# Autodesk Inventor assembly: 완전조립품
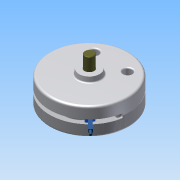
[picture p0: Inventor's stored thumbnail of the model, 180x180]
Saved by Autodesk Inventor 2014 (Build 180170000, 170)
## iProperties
Created: 2015-06
Part Number: 완전조립품
Document SubType Name: Assembly
Designer: Administrator
Author: Administrator
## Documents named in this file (10)
- C:\Documents and Settings\Administrator\바탕 화면\450631V1008\완전조립품.iam
- C:\Documents and Settings\Administrator\바탕 화면\450631V1008\본체.ipt
- C:\Documents and Settings\Administrator\바탕 화면\450631V1008\덮개.ipt
- C:\Documents and Settings\Administrator\바탕 화면\450631V1008\베어링62_22.ipt
- C:\Documents and Settings\Administrator\바탕 화면\450631V1008\슬라이더2.ipt
- C:\Documents and Settings\Administrator\바탕 화면\450631V1008\축.ipt
- C:\Documents and Settings\Administrator\바탕 화면\450631V1008\멈춤링.ipt
- C:\Documents and Settings\Administrator\바탕 화면\450631V1008\슬라이더.ipt
- C:\Documents and Settings\Administrator\바탕 화면\450631V1008\평행핀.ipt
- C:\Documents and Settings\Administrator\바탕 화면\450631V1008\M10x35.ipt
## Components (7 placed, 4 different names)
1. KS B 2023 62/22 - 22 x 50 x 14:1
2. KS B 2023 62/22 - 22 x 50 x 14:2
3. KS B 1336 22 x 1.2:1
4. KS B 1336 22 x 1.2:2
5. KS B 1320 B B 5 x  20:1
6. KS B 1003 - 미터 M 10 x 35:1
7. KS B 1003 - 미터 M 10 x 35:2
